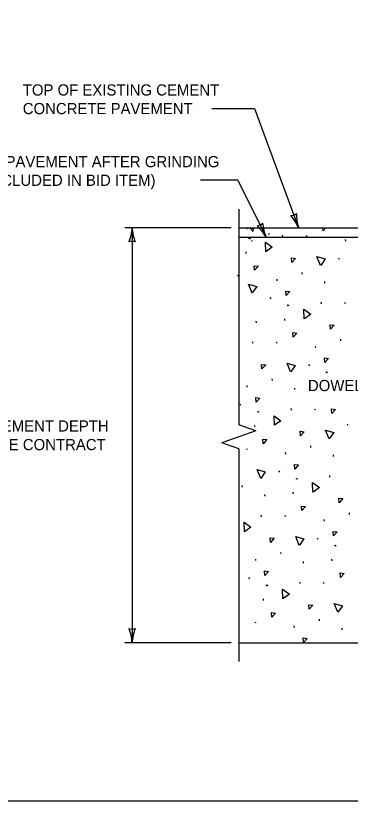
# Model space of a CAD drawing. Extents: x 49991.4 to 50021, y 49987.6 to 50011.4.
# Drawn here: x 50001.317 to 50003.117, y 49987.799 to 49992.017 of the extents above; entities that cross this region are included whole.
import ezdxf

# ---------------------------------------------------------------- set-up
doc = ezdxf.new("R2010")
doc.units = 0
for name, color, linetype in [('Level 1', 7, 'Continuous'), ('Level 2', 7, 'Continuous'), ('Level 3', 7, 'Continuous'), ('Level 4', 7, 'Continuous'), ('Level 6', 7, 'Continuous')]:
    doc.layers.add(name, color=color, linetype=linetype)

msp = doc.modelspace()

# ---------------------------------------------------------------- linework, layer by layer
at = {"layer": 'Level 1'}
for p, q in [((50002.5169, 49990.8781), (50003.5758, 49990.8781)), ((50002.5169, 49990.8281), (50005.421, 49990.8281)), ((50002.5169, 49988.6501), (50005.421, 49988.6501))]:
    msp.add_line(p, q, dxfattribs=at)
msp.add_lwpolyline([(49999.3835, 49998.9992), (50016.7501, 49998.9992), (50016.7501, 49987.7988), (49999.3835, 49987.7988)], close=True, dxfattribs=at)
at = {"layer": 'Level 3'}
for p, q in [((50002.3723, 49991.5185), (50002.6014, 49991.5185)), ((50002.5114, 49991.1336), (50002.3114, 49991.1336)), ((50002.4769, 49990.8781), (50001.9037, 49990.8781)), ((50001.9437, 49990.8781), (50001.9437, 49988.6503)), ((50002.4769, 49988.6503), (50001.9037, 49988.6503))]:
    msp.add_line(p, q, dxfattribs=at)
for points in [[(50002.6014, 49991.5185), (50002.8389, 49990.8777)], [(50002.5114, 49991.1336), (50002.665, 49990.8281)]]:
    msp.add_lwpolyline(points, dxfattribs=at)
for centre, radius, start, end in [((50002.7942, 49990.9983), 0.0548, 272.4715, 308.1939), ((50003.0502, 49990.9467), 0.2223, 177.7887, 197.9722), ((50002.6245, 49990.7865), 0.233, 23.16, 42.4099), ((50001.7215, 49990.8873), 0.2223, 337.456, 357.6395), ((50002.1764, 49990.8896), 0.233, 182.8273, 202.0772), ((50002.6074, 49990.9427), 0.0548, 278.8313, 314.5536), ((50002.4622, 49990.7133), 0.233, 29.5197, 48.7696), ((50002.8675, 49990.9197), 0.2223, 184.1484, 204.332), ((50001.9437, 49990.7499), 0.0548, 72.1388, 107.8612), ((50001.9437, 49988.7785), 0.0548, 252.1388, 287.8612), ((50001.7109, 49988.6388), 0.233, 2.8273, 22.0772), ((50002.1658, 49988.6411), 0.2223, 157.456, 177.6395)]:
    msp.add_arc(centre, radius, start, end, dxfattribs=at)
at = {"layer": 'Level 4'}
for p, q in [((50002.5702, 49990.8232), (50002.5759, 49990.8204)), ((50002.5743, 49990.8232), (50002.58, 49990.8204)), ((50002.6819, 49990.8485), (50002.6771, 49990.842)), ((50002.754, 49990.8298), (50002.7531, 49990.8385)), ((50002.8786, 49990.8361), (50002.8843, 49990.8332)), ((50002.5891, 49990.8089), (50002.5833, 49990.8061)), ((50003.0924, 49990.8067), (50003.0915, 49990.8154)), ((50002.5577, 49990.74), (50002.5568, 49990.7487)), ((50003.0531, 49990.7162), (50003.0579, 49990.7098)), ((50002.5102, 49990.6234), (50002.5159, 49990.6205)), ((50002.8591, 49990.63), (50002.8582, 49990.6387)), ((50002.724, 49990.594), (50002.7231, 49990.6027)), ((50002.9806, 49990.5812), (50002.9797, 49990.5899)), ((50002.6847, 49990.5036), (50002.6895, 49990.4971)), ((50002.7776, 49990.464), (50002.7833, 49990.4611)), ((50002.7817, 49990.464), (50002.7874, 49990.4612)), ((50002.9614, 49990.4705), (50002.9605, 49990.4792)), ((50003.086, 49990.4768), (50003.0917, 49990.474)), ((50002.6122, 49990.3685), (50002.6113, 49990.3772)), ((50002.7651, 49990.3808), (50002.7642, 49990.3895)), ((50003.0665, 49990.2708), (50003.0656, 49990.2795)), ((50002.5931, 49990.2579), (50002.5921, 49990.2666)), ((50002.7176, 49990.2641), (50002.7233, 49990.2613)), ((50002.9314, 49990.2348), (50002.9305, 49990.2435)), ((50002.8921, 49990.1443), (50002.8969, 49990.1378)), ((50002.6981, 49990.0581), (50002.6972, 49990.0668)), ((50002.985, 49990.1047), (50002.9907, 49990.1019)), ((50002.9891, 49990.1048), (50002.9948, 49990.1019)), ((50002.563, 49990.0221), (50002.5621, 49990.0308)), ((50002.8196, 49990.0093), (50002.8187, 49990.018)), ((50002.5238, 49989.9316), (50002.5285, 49989.9252)), ((50002.8005, 49989.8986), (50002.7995, 49989.9073)), ((50002.925, 49989.9049), (50002.9308, 49989.9021)), ((50002.6166, 49989.8921), (50002.6223, 49989.8892)), ((50002.6207, 49989.8921), (50002.6264, 49989.8892)), ((50002.6041, 49989.8088), (50002.6032, 49989.8175)), ((50003.0996, 49989.8251), (50003.1043, 49989.8186)), ((50002.5566, 49989.6922), (50002.5624, 49989.6894)), ((50002.9056, 49989.6988), (50002.9046, 49989.7075)), ((50002.7705, 49989.6629), (50002.7695, 49989.6716)), ((50003.027, 49989.65), (50003.0261, 49989.6587)), ((50002.7312, 49989.5724), (50002.7359, 49989.5659)), ((50002.824, 49989.5328), (50002.8297, 49989.53)), ((50002.8281, 49989.5328), (50002.8338, 49989.53)), ((50003.0079, 49989.5394), (50003.007, 49989.5481)), ((50002.5372, 49989.4861), (50002.5363, 49989.4948)), ((50002.6587, 49989.4373), (50002.6577, 49989.446)), ((50002.8115, 49989.4496), (50002.8106, 49989.4583)), ((50003.113, 49989.3396), (50003.112, 49989.3483)), ((50002.6395, 49989.3267), (50002.6386, 49989.3354)), ((50002.764, 49989.333), (50002.7698, 49989.3301)), ((50002.9779, 49989.3036), (50002.9769, 49989.3123)), ((50002.9386, 49989.2132), (50002.9433, 49989.2067)), ((50002.7446, 49989.1269), (50002.7437, 49989.1356)), ((50003.0314, 49989.1736), (50003.0372, 49989.1707)), ((50003.0355, 49989.1736), (50003.0412, 49989.1708)), ((50002.6095, 49989.091), (50002.6086, 49989.0996)), ((50003.0189, 49989.0904), (50003.018, 49989.0991)), ((50002.8661, 49989.0781), (50002.8651, 49989.0868)), ((50002.5702, 49989.0005), (50002.575, 49988.994)), ((50002.8469, 49988.9674), (50002.846, 49988.9761)), ((50002.9714, 49988.9737), (50002.9772, 49988.9709)), ((50002.663, 49988.9609), (50002.6688, 49988.958)), ((50002.6671, 49988.9609), (50002.6729, 49988.9581)), ((50002.6506, 49988.8777), (50002.6496, 49988.8864)), ((50002.6031, 49988.761), (50002.6088, 49988.7582)), ((50002.952, 49988.7677), (50002.9511, 49988.7764)), ((50002.8169, 49988.7317), (50002.816, 49988.7404)), ((50003.0735, 49988.7189), (50003.0726, 49988.7276))]:
    msp.add_line(p, q, dxfattribs=at)
for points in [[(50002.5648, 49990.8734), (50002.5644, 49990.8781)], [(50002.5691, 49990.8781), (50002.5648, 49990.8734)], [(50002.577, 49990.8781), (50002.5944, 49990.8591)], [(50002.5944, 49990.8591), (50002.5959, 49990.8781)], [(50002.9709, 49990.8627), (50002.9697, 49990.8781)], [(50002.9851, 49990.8781), (50002.9709, 49990.8627)], [(50002.6622, 49990.7491), (50002.6603, 49990.8003), (50002.6973, 49990.7735), (50002.663, 49990.7495)], [(50002.8028, 49990.6924), (50002.8009, 49990.7169), (50002.823, 49990.7143), (50002.8028, 49990.6924)], [(50002.9573, 49990.6761), (50002.938, 49990.7235), (50002.982, 49990.711), (50002.9579, 49990.6767)], [(50002.6025, 49990.65), (50002.6006, 49990.6746), (50002.6227, 49990.6719), (50002.6025, 49990.65)], [(50002.5889, 49990.5276), (50002.5696, 49990.5751), (50002.6136, 49990.5626), (50002.5895, 49990.5283)], [(50002.7722, 49990.5142), (50002.7703, 49990.5387), (50002.7924, 49990.5361), (50002.7722, 49990.5142)], [(50002.8696, 49990.3898), (50002.8677, 49990.441), (50002.9048, 49990.4142), (50002.8704, 49990.3903)], [(50003.0102, 49990.3331), (50003.0084, 49990.3577), (50003.0304, 49990.355), (50003.0102, 49990.3331)], [(50002.8099, 49990.2908), (50002.808, 49990.3153), (50002.8301, 49990.3127), (50002.8099, 49990.2908)], [(50002.7963, 49990.1041), (50002.777, 49990.1516), (50002.821, 49990.1391), (50002.7969, 49990.1048)], [(50002.9796, 49990.1549), (50002.9777, 49990.1795), (50002.9998, 49990.1768), (50002.9796, 49990.1549)], [(50002.6418, 49990.1204), (50002.64, 49990.145), (50002.662, 49990.1423), (50002.6418, 49990.1204)], [(50002.6112, 49989.9423), (50002.6093, 49989.9668), (50002.6314, 49989.9642), (50002.6112, 49989.9423)], [(50003.0173, 49989.8808), (50003.0154, 49989.9054), (50003.0375, 49989.9027), (50003.0173, 49989.8808)], [(50002.7086, 49989.8179), (50002.7068, 49989.8691), (50002.7438, 49989.8423), (50002.7094, 49989.8184)], [(50002.8492, 49989.7612), (50002.8474, 49989.7857), (50002.8694, 49989.7831), (50002.8492, 49989.7612)], [(50003.0037, 49989.7449), (50002.9844, 49989.7924), (50003.0284, 49989.7798), (50003.0043, 49989.7456)], [(50002.6489, 49989.7188), (50002.6471, 49989.7434), (50002.6691, 49989.7407), (50002.6489, 49989.7188)], [(50002.8186, 49989.583), (50002.8167, 49989.6076), (50002.8388, 49989.6049), (50002.8186, 49989.583)], [(50002.6353, 49989.5322), (50002.616, 49989.5797), (50002.66, 49989.5671), (50002.6359, 49989.5329)], [(50002.916, 49989.4587), (50002.9142, 49989.5099), (50002.9512, 49989.4831), (50002.9168, 49989.4591)], [(50003.0567, 49989.402), (50003.0548, 49989.4265), (50003.0768, 49989.4239), (50003.0567, 49989.402)], [(50002.8563, 49989.3596), (50002.8545, 49989.3841), (50002.8765, 49989.3815), (50002.8563, 49989.3596)], [(50002.5477, 49989.246), (50002.5458, 49989.2972), (50002.5828, 49989.2704), (50002.5484, 49989.2464)], [(50002.8427, 49989.173), (50002.8235, 49989.2204), (50002.8674, 49989.2079), (50002.8433, 49989.1736)], [(50003.026, 49989.2238), (50003.0242, 49989.2483), (50003.0462, 49989.2457), (50003.026, 49989.2238)], [(50002.6883, 49989.1893), (50002.6864, 49989.2138), (50002.7084, 49989.2112), (50002.6883, 49989.1893)], [(50002.6576, 49989.0111), (50002.6558, 49989.0356), (50002.6778, 49989.033), (50002.6576, 49989.0111)], [(50003.0637, 49989.0004), (50003.0619, 49989.0249), (50003.0839, 49989.0223), (50003.0637, 49989.0004)], [(50002.7551, 49988.8867), (50002.7532, 49988.9379), (50002.7902, 49988.9111), (50002.7558, 49988.8872)], [(50002.8957, 49988.83), (50002.8938, 49988.8546), (50002.9158, 49988.8519), (50002.8957, 49988.83)], [(50003.0501, 49988.8137), (50003.0309, 49988.8612), (50003.0748, 49988.8487), (50003.0507, 49988.8144)], [(50002.6954, 49988.7877), (50002.6935, 49988.8122), (50002.7155, 49988.8096), (50002.6954, 49988.7877)], [(50002.865, 49988.6518), (50002.8632, 49988.6764), (50002.8852, 49988.6737), (50002.865, 49988.6518)]]:
    msp.add_lwpolyline(points, dxfattribs=at)
at = {"layer": 'Level 6'}
for p, q in [((50002.5169, 49990.9781), (50002.5169, 49989.821)), ((50002.6083, 49989.7886), (50002.5169, 49989.821)), ((50002.6083, 49989.7886), (50002.5169, 49989.7562)), ((50002.5169, 49989.7562), (50002.4255, 49989.7238)), ((50002.5169, 49989.6914), (50002.4255, 49989.7238)), ((50002.5169, 49989.6914), (50002.5169, 49988.5501))]:
    msp.add_line(p, q, dxfattribs=at)

# ---------------------------------------------------------------- texts
at = {"layer": 'Level 2'}
for s, p in [('TOP OF EXISTING CEMENT', (50001.3554, 49991.5885)), ('CONCRETE PAVEMENT', (50001.3554, 49991.4885)), ('DOWEL BAR', (50002.8893, 49990.0014)), ('PAVEMENT DEPTH', (50001.082, 49989.7842)), ('VARIES SEE CONTRACT', (50000.8563, 49989.6842))]:
    msp.add_text(s, height=0.06, dxfattribs=at).set_placement(p)
for s, p in [('TOP OF PAVEMENT AFTER GRINDING', (50000.9417, 49991.2036)), ('(NOT INCLUDED IN BID ITEM)', (50000.9417, 49991.1036))]:
    msp.add_text(s, height=0.06, rotation=360, dxfattribs=at).set_placement(p)

doc.saveas('drawing.dxf')
